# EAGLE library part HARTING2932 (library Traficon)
Harting TB 09 06 115 2932 DIN41612 type H, 15 pins male plug
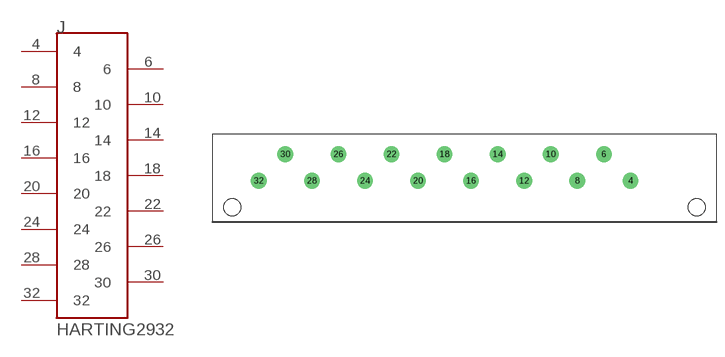
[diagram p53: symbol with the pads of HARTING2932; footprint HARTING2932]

Designator prefix J

## HARTING2932  [HARTING2932]
4  4
6  6
8  8
10  10
12  12
14  14
16  16
18  18
20  20
22  22
24  24
26  26
28  28
30  30
32  32

## Footprint HARTING2932 (pad centres in mm)
drill 2 round: 4 31.75,0; 6 26.67,5.08; 8 21.59,0; 10 16.51,5.08; 12 11.43,0; 14 6.35,5.08; 16 1.27,0; 18 -3.81,5.08; 20 -8.89,0; 22 -13.97,5.08; 24 -19.05,0; 26 -24.13,5.08; 28 -29.21,0; 30 -34.29,5.08; 32 -39.37,0
hole 3.2 at 44.45,-5.08
hole 3.2 at -44.45,-5.08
